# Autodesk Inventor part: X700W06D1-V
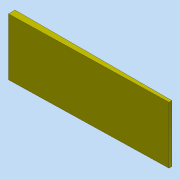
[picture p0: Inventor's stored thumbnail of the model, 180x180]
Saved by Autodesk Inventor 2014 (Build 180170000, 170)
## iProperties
Created: 2012-02
Part Number: X700W06D1-V
Document SubType Name: Modeling
Designer: david.appleford
Density: 1 g/cm^3
Description: 1.5w EPS Wedge 1046mm - First Slope
Mass: 77280 g
Surface Area: 29896.7 cm^2
Volume: 77280 cm^3
Cost Center: £14.00
Material: Generic
Appearance: Stucco_01
Justset: False
Title: 1.5w EPS Wedge 1046mm - First Slope
Author: david.appleford
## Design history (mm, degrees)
sketch "Sketch1"
  geometry: L1 (1883.416, -41.062)-(1883.416, -76.062); L2 (1883.416, -76.062)-(-36.584, -121.062); L3 (1883.416, -41.062)-(-36.584, -41.062); L4 (-36.584, -121.062)-(-36.584, -41.062)
  constraints: 8 end point, 1 horizontal, 1 perpendicular
  dimensions: "d0" = 35 distance from line of L1.end L3; "d21" = 1920 distance between parallel lines of L1 L4; "d22" = 80 distance of L2.end L3.end
extrude "Extrusion1" new body sketch "Sketch1" distance "d4" = 700; taper "d5" = 0 deg
body "Solid1"
